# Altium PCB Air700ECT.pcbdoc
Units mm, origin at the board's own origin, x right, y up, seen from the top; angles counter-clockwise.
Board outline 24.15 x 27.15 mm, 2 copper layers (Top Layer, Bottom Layer), stack 1.58 mm thick; 1 components, 0 nets, 80 pads, 0 vias.
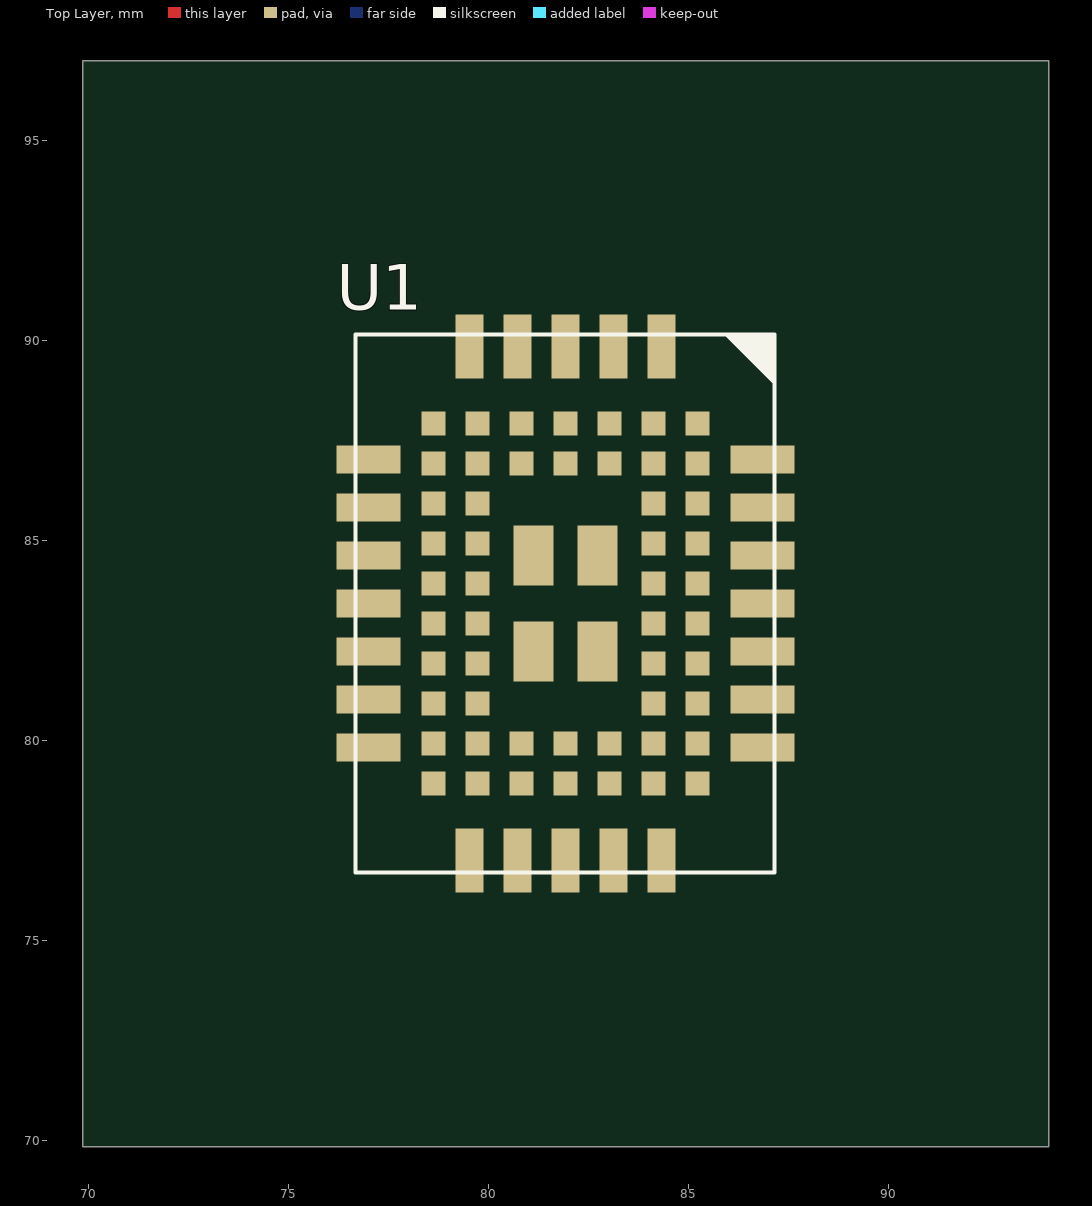
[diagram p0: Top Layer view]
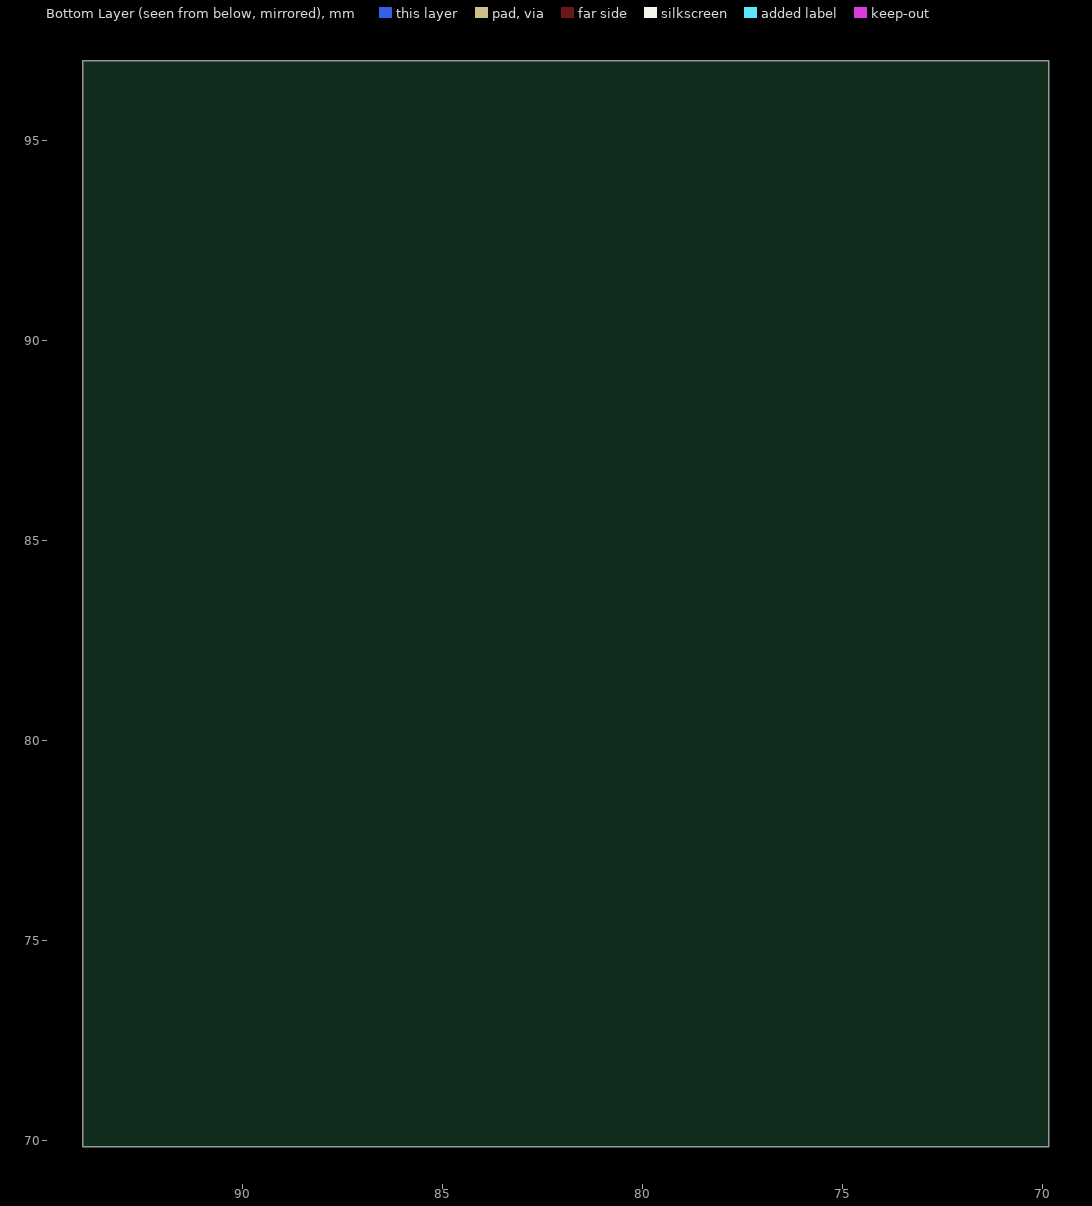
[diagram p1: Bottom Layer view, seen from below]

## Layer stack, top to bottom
Top Solder Mask Layer: solder mask 0.01, Dk 3.3
Top Layer: signal copper 0.035
Dielectric1: surface 1.51, FR4, Dk 4.5
Bottom Layer: signal copper 0.035
Bottom Solder Mask Layer: solder mask 0.01, Dk 3.3

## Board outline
94,69.85 69.85,69.85 69.85,97 94,97

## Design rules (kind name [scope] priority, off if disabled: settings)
BoardOutlineClearance copperThickness1oz [All] p0: genericclearance=0.254 ignorepadtopadclearanceinfootprint=FALSE except(0: Arc-SplitContinuation Track-SplitContinuation SMDPad-SplitContinuation THPad-SplitContinuation Via-SplitContinuation Fill-SplitContinuation Poly-SplitContinuation Region-SplitContinuation Text-SplitContinuation)
BoardOutlineClearance copperThickness2oz [All] p0: genericclearance=0.254 ignorepadtopadclearanceinfootprint=FALSE except(0: Arc-SplitContinuation Track-SplitContinuation SMDPad-SplitContinuation THPad-SplitContinuation Via-SplitContinuation Fill-SplitContinuation Poly-SplitContinuation Region-SplitContinuation Text-SplitContinuation)
BoardOutlineClearance otherClearance [All] p0: genericclearance=0.254 ignorepadtopadclearanceinfootprint=FALSE except(0: Arc-SplitContinuation Track-SplitContinuation SMDPad-SplitContinuation THPad-SplitContinuation Via-SplitContinuation Fill-SplitContinuation Poly-SplitContinuation Region-SplitContinuation Text-SplitContinuation)
Clearance copperThickness1oz [All] p1: gap=0.178 ignorepadtopadclearanceinfootprint=FALSE
Clearance copperThickness2oz [All] p1: gap=0.178 ignorepadtopadclearanceinfootprint=FALSE
Clearance otherClearance [All] p1: gap=0.178 ignorepadtopadclearanceinfootprint=FALSE
DiffPairsRouting differentialPair [All] p1: maxuncoupledlength=10 minlimit=6 maxlimit=Infinity mostfreqgap=6 toplayer_minwidth=5 toplayer_prefwidth=10 toplayer_maxwidth=100 bottomlayer_minwidth=5 bottomlayer_prefwidth=10 bottomlayer_maxwidth=100
PasteMaskExpansion pasteMaskExpansion [All] p1: expansion=0
PlaneConnect innerPlane [All] p1: planeconnectstyle=Relief reliefexpansion=0.508 reliefentries=4 reliefconductorwidth=0.254 reliefairgap=0.254
PolygonConnect copperRegion [All] p1: connectstyle=Relief reliefentries=4 reliefconductorwidth=10 polygonreliefangle="90 Angle" airgapwidth=10
RoutingVias viaSize [All] p1: viastyle="Through Hole" holewidth=12.0078 minholewidth=11.811 maxholewidth=248.0314 width=12.0078 minwidth=11.811 maxwidth=248.0314
SolderMaskExpansion solderMaskExpansion [All] p1: useseparateexpansions=TRUE expansion=2 expansionbottom=2
Width copperThickness1oz [All] p1: maxlimit=100 minlimit=5 preferedwidth=10
Width copperThickness2oz [All] p1: maxlimit=100 minlimit=8 preferedwidth=10

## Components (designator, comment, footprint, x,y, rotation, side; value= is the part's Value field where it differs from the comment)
U1 "" AIR700ECT 81.925,83.425 r0 top

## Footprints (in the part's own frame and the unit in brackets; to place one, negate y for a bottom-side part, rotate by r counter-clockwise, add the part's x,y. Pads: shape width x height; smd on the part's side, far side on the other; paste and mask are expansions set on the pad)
AIR700ECT [mm]
  rect 0.7x1.6 smd: 1(2.4,6.425) 2(1.2,6.425) 3(0,6.425) 4(-1.2,6.425) 5(-2.4,6.425) 13(-2.4,-6.425) 14(-1.2,-6.425) 15(0,-6.425) 16(1.2,-6.425) 17(2.4,-6.425)
  rect 1.6x0.7 smd: 6(-4.925,3.6) 7(-4.925,2.4) 8(-4.925,1.2) 9(-4.925,0) 10(-4.925,-1.2) 11(-4.925,-2.4) 12(-4.925,-3.6) 18(4.925,-3.6) 19(4.925,-2.4) 20(4.925,-1.2) 21(4.925,0) 22(4.925,1.2) 23(4.925,2.4) 24(4.925,3.6)
  rect 0.6x0.6 smd: 25(3.3,4.5) 26(2.2,4.5) 27(1.1,4.5) 28(0,4.5) 29(-1.1,4.5) 30(-2.2,4.5) 31(-3.3,4.5) 32(-3.3,3.5) 33(-3.3,2.5) 34(-3.3,1.5) 35(-3.3,0.5) 36(-3.3,-0.5) 37(-3.3,-1.5) 38(-3.3,-2.5) 39(-3.3,-3.5) 40(-3.3,-4.5) 41(-2.2,-4.5) 42(-1.1,-4.5) 43(0,-4.5) 44(1.1,-4.5) 45(2.2,-4.5) 46(3.3,-4.5) 47(3.3,-3.5) 48(3.3,-2.5) 49(3.3,-1.5) 50(3.3,-0.5) 51(3.3,0.5) 52(3.3,1.5) 53(3.3,2.5) 54(3.3,3.5) 55(2.2,3.5) 56(1.1,3.5) 57(0,3.5) 58(-1.1,3.5) 59(-2.2,3.5) 60(-2.2,2.5) 61(-2.2,1.5) 62(-2.2,0.5) 63(-2.2,-0.5) 64(-2.2,-1.5) 65(-2.2,-2.5) 66(-2.2,-3.5) 67(-1.1,-3.5) 68(0,-3.5) 69(1.1,-3.5) 70(2.2,-3.5) 71(2.2,-2.5) 72(2.2,-1.5) 73(2.2,-0.5) 74(2.2,0.5) 75(2.2,1.5) 76(2.2,2.5)
  rect 1x1.5 smd: 77(0.8,1.2) 78(-0.8,1.2) 79(-0.8,-1.2) 80(0.8,-1.2)
  silkscreen extent -5.25,-6.73 5.23,6.73

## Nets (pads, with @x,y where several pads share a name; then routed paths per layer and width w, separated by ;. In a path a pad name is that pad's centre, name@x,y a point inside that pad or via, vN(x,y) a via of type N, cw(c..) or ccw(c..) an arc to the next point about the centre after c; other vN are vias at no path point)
pads on no net: U1.1 U1.2 U1.3 U1.4 U1.5 U1.6 U1.7 U1.8 U1.9 U1.10 U1.11 U1.12 U1.13 U1.14 U1.15 U1.16 U1.17 U1.18 U1.19 U1.20 U1.21 U1.22 U1.23 U1.24 U1.25 U1.26 U1.27 U1.28 U1.29 U1.30 U1.31 U1.32 U1.33 U1.34 U1.35 U1.36 U1.37 U1.38 U1.39 U1.40 U1.41 U1.42 U1.43 U1.44 U1.45 U1.46 U1.47 U1.48 U1.49 U1.50 U1.51 U1.52 U1.53 U1.54 U1.55 U1.56 U1.57 U1.58 U1.59 U1.60 U1.61 U1.62 U1.63 U1.64 U1.65 U1.66 U1.67 U1.68 U1.69 U1.70 U1.71 U1.72 U1.73 U1.74 U1.75 U1.76 U1.77 U1.78 U1.79 U1.80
